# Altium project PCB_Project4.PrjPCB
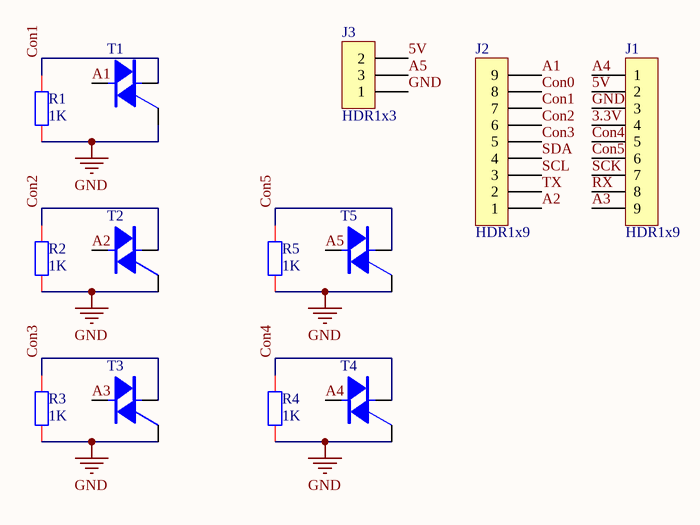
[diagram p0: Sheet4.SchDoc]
1 sheet, 13 parts. Net scope: global (net labels, ports and power ports of the same name join across sheets).
Board files: PCB4.PcbDoc, PCB4-1.PcbDoc, PCB_LED2.PcbDoc, PCB_LED.PcbDoc

## Sheet Sheet4.SchDoc
size A4

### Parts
J1  HDR1x9  [PIN-9-2.54-1.0]
J2  HDR1x9  [PIN-9-2.54-1.0]
J3  HDR1x3  [PIN-3-2.54-1.0]
R1  value 1K  [0603]  (hidden comment: Res2)
R2  value 1K  [0603]  (hidden comment: Res2)
R3  value 1K  [0603]  (hidden comment: Res2)
R4  value 1K  [0603]  (hidden comment: Res2)
R5  value 1K  [0603]  (hidden comment: Res2)
T1  BT136S-600E  [TO-252]  (value not drawn)
T2  BT136S-600E  [TO-252]  (value not drawn)
T3  BT136S-600E  [TO-252]  (value not drawn)
T4  BT136S-600E  [TO-252]  (value not drawn)
T5  BT136S-600E  [TO-252]  (value not drawn)

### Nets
GND: J1.3 J3.1 R1.1 R2.1 R3.1 R4.1 R5.1 T1.3(G) T2.3(G) T3.3(G) T4.3(G) T5.3(G)
3.3V: J1.4
5V: J1.2 J3.2
A1: J2.9 T1.4(T2)
A2: J2.1 T2.4(T2)
A3: J1.9 T3.4(T2)
A4: J1.1 T4.4(T2)
A5: J3.3 T5.4(T2)
Con0: J2.8
Con1: J2.7 R1.2 T1.1(T1)
Con2: J2.6 R2.2 T2.1(T1)
Con3: J2.5 R3.2 T3.1(T1)
Con4: J1.5 R4.2 T4.1(T1)
Con5: J1.6 R5.2 T5.1(T1)
RX: J1.8
SCK: J1.7
SCL: J2.3
SDA: J2.4
TX: J2.2

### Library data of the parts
J1 J2 = HDR1x9: Connector
J3 = HDR1x3: Connector
R1-R5 = Res2: Resistor
T1-T5 = BT136S-600E: Triac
